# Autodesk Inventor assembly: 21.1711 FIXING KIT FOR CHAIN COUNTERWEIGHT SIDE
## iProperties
Created: 2007-05
Part Number: 21.1711 FIXING KIT FOR CHAIN COUNTERWEIGHT SIDE
Document SubType Name: Assembly
Designer: Andy Moles
Mass: 15.828 g
Surface Area: 45.9165 cm^2
Volume: 5.84327 cm^3
Density: 2.70875 g/cm^3
Author: Andy Moles
